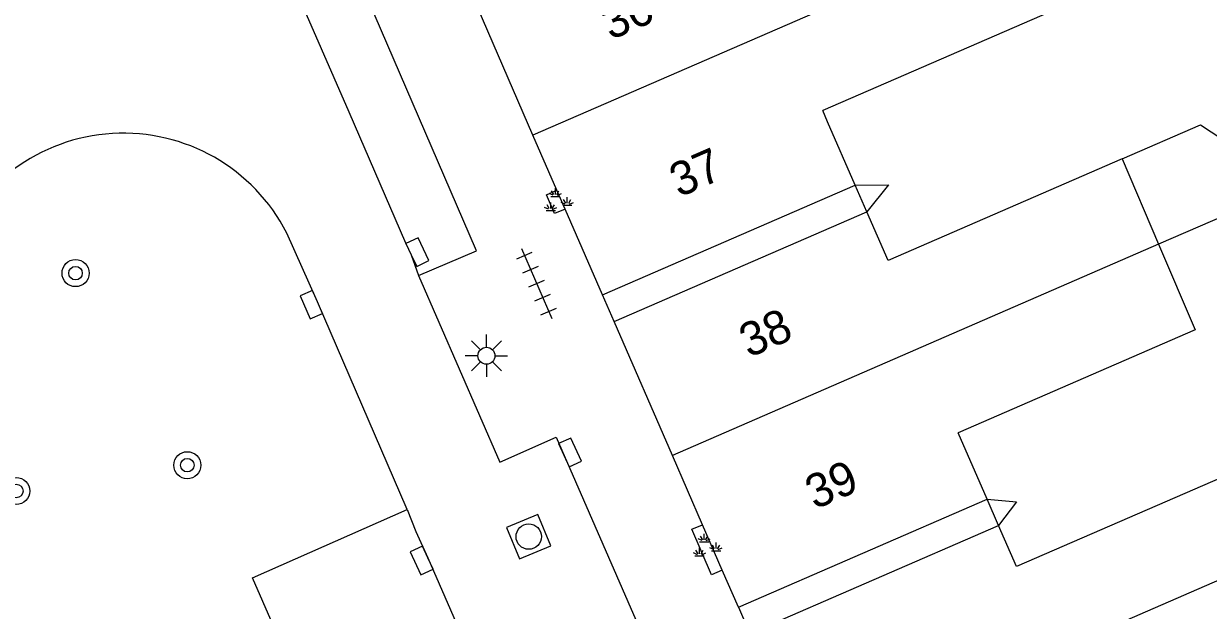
# Model space of a CAD drawing. Extents: x 132998 to 136004, y 396998 to 398512.
# Drawn here: x 133200.28 to 133235.3, y 397162.85 to 397180.2 of the extents above; entities that cross this region are included whole.
import ezdxf

# ---------------------------------------------------------------- set-up
doc = ezdxf.new("R2010")
doc.units = 0
for name, color, linetype in [('gg-afsc-erfafscheiding', 7, 'Continuous'), ('gg-anno-huisnummerreeks BGT', 7, 'Continuous'), ('gg-bbg-gedigitaliseerde bebouwing', 7, 'Continuous'), ('gg-bbg-gedigitaliseerde bebouwing onder overbouw', 7, 'Continuous'), ('gg-bbg-gedigitaliseerde overbouw', 7, 'Continuous'), ('gg-bbg-hoofdgebouw', 7, 'Continuous'), ('gg-bbg-luifel en loopbrug', 7, 'Continuous'), ('gg-bbg-pand overbouw', 7, 'Continuous'), ('gg-bbg-tussenscheiding', 7, 'Continuous'), ('gg-knt-verharding', 7, 'Continuous'), ('gg-knt-verharding nz', 7, 'Continuous'), ('gt-symb-boom', 7, 'Continuous'), ('gt-symb-groenvak', 7, 'Continuous'), ('gt-symb-kolk', 7, 'Continuous'), ('gt-symb-lichtmast', 7, 'Continuous'), ('gt-symb-rioolschacht', 7, 'Continuous'), ('gt-symb-tegel verharding', 7, 'Continuous')]:
    doc.layers.add(name, color=color, linetype=linetype)

# ---------------------------------------------------------------- blocks, each defined once
blk = doc.blocks.new('gt0-GRVAK')
at = {"layer": 'gt-symb-groenvak'}
for p, q in [((-0.047, 0.214), (-0.047, 0.393)), ((-0.11, 0.189), (-0.228, 0.24)), ((-0.182, 0.153), (0.088, 0.153)), ((-0.091, 0.211), (-0.156, 0.322)), ((-0.004, 0.211), (0.061, 0.322)), ((0.015, 0.189), (0.133, 0.24)), ((0.262, -0.052), (0.197, 0.059)), ((0.305, -0.049), (0.305, 0.13)), ((0.349, -0.052), (0.414, 0.059)), ((-0.245, -0.228), (-0.363, -0.177)), ((-0.318, -0.264), (-0.047, -0.264)), ((-0.226, -0.206), (-0.291, -0.095)), ((-0.183, -0.203), (-0.183, -0.024)), ((-0.139, -0.206), (-0.074, -0.095)), ((-0.12, -0.228), (-0.002, -0.177)), ((0.243, -0.074), (0.125, -0.023)), ((0.17, -0.11), (0.441, -0.11)), ((0.368, -0.074), (0.486, -0.023))]:
    blk.add_line(p, q, dxfattribs=at)
blk = doc.blocks.new('gt0-KOLK')
at = {"layer": 'gt-symb-kolk'}
blk.add_lwpolyline([(0, 0), (0.375, 0), (0.375, 0.4), (-0.375, 0.4), (-0.375, 0), (0, 0)], dxfattribs=at)
blk = doc.blocks.new('gt0-BOOM')
at = {"layer": 'gt-symb-boom'}
for radius in [0.4, 0.2]:
    blk.add_circle((0, 0), radius, dxfattribs=at)
blk = doc.blocks.new('gt0-LMAST')
at = {"layer": 'gt-symb-lichtmast'}
for p, q in [((-0.182, 0.173), (-0.447, 0.438)), ((-0.005, 0.246), (-0.005, 0.621)), ((0.172, 0.173), (0.437, 0.438)), ((-0.255, -0.004), (-0.63, -0.004)), ((-0.182, -0.181), (-0.447, -0.446)), ((-0.005, -0.254), (-0.005, -0.629)), ((0.437, -0.446), (0.172, -0.181)), ((0.245, -0.004), (0.62, -0.004))]:
    blk.add_line(p, q, dxfattribs=at)
blk.add_circle((-0.005, -0.004), 0.25, dxfattribs=at)
blk = doc.blocks.new('gt0-TEG1')
at = {"layer": 'gt-symb-tegel verharding'}
for p, q in [((-1.125, 0), (1.125, 0)), ((-0.9, -0.25), (-0.9, 0.25)), ((-0.45, -0.25), (-0.45, 0.25)), ((0, -0.25), (0, 0.25)), ((0.45, -0.25), (0.45, 0.25)), ((0.9, -0.25), (0.9, 0.25))]:
    blk.add_line(p, q, dxfattribs=at)
blk = doc.blocks.new('gt0-RS')
at = {"layer": 'gt-symb-rioolschacht'}
blk.add_lwpolyline([(-0.5, -0.5), (0.5, -0.5), (0.5, 0.5), (-0.5, 0.5)], close=True, dxfattribs=at)
blk.add_circle((0, 0), 0.375, dxfattribs=at)

msp = doc.modelspace()

# ---------------------------------------------------------------- linework, layer by layer
at = {"layer": 'gg-afsc-erfafscheiding'}
for points in [[(133224.863, 397175.424), (133225.843, 397175.433), (133225.204, 397174.64)], [(133228.762, 397166.135), (133229.632, 397166.06), (133229.1, 397165.358)]]:
    msp.add_lwpolyline(points, dxfattribs=at)
at = {"layer": 'gg-bbg-gedigitaliseerde bebouwing'}
for p, q in [((133231.428, 397180.9), (133223.903, 397177.63)), ((133224.046, 397177.302), (133223.903, 397177.63)), ((133224.863, 397175.424), (133224.046, 397177.302)), ((133232.753, 397176.204), (133225.833, 397173.196)), ((133232.753, 397176.204), (133233.831, 397173.675)), ((133225.833, 397173.196), (133225.204, 397174.64)), ((133233.831, 397173.675), (133234.91, 397171.145)), ((133234.91, 397171.145), (133227.907, 397168.101)), ((133228.762, 397166.135), (133227.907, 397168.101)), ((133229.628, 397164.144), (133229.1, 397165.358))]:
    msp.add_line(p, q, dxfattribs=at)
msp.add_lwpolyline([(133237.519, 397167.139), (133237.354, 397167.503), (133229.628, 397164.144)], dxfattribs=at)
at = {"layer": 'gg-bbg-gedigitaliseerde bebouwing onder overbouw'}
for p, q in [((133217.394, 397172.177), (133224.863, 397175.424)), ((133217.735, 397171.393), (133225.204, 397174.64)), ((133221.41, 397162.939), (133228.762, 397166.135)), ((133221.748, 397162.162), (133229.1, 397165.358))]:
    msp.add_line(p, q, dxfattribs=at)
at = {"layer": 'gg-bbg-gedigitaliseerde overbouw'}
for p, q in [((133225.204, 397174.64), (133224.863, 397175.424)), ((133229.1, 397165.358), (133228.762, 397166.135))]:
    msp.add_line(p, q, dxfattribs=at)
at = {"layer": 'gg-bbg-hoofdgebouw'}
for p, q in [((133215.339, 397176.905), (133213.717, 397180.636)), ((133216.047, 397175.276), (133215.339, 397176.905)), ((133216.29, 397174.718), (133216.047, 397175.276)), ((133217.394, 397172.177), (133216.29, 397174.718)), ((133219.459, 397167.427), (133217.735, 397171.393)), ((133220.347, 397165.383), (133219.459, 397167.427)), ((133220.934, 397164.034), (133220.347, 397165.383)), ((133221.41, 397162.939), (133220.934, 397164.034))]:
    msp.add_line(p, q, dxfattribs=at)
at = {"layer": 'gg-bbg-luifel en loopbrug'}
msp.add_lwpolyline([(133232.753, 397176.204), (133235.068, 397177.211), (133237.816, 397175.407), (133233.831, 397173.675)], dxfattribs=at)
at = {"layer": 'gg-bbg-pand overbouw'}
for p, q in [((133217.735, 397171.393), (133217.394, 397172.177)), ((133221.41, 397162.939), (133221.748, 397162.162))]:
    msp.add_line(p, q, dxfattribs=at)
at = {"layer": 'gg-bbg-tussenscheiding'}
for p, q in [((133228.773, 397182.745), (133215.339, 397176.905)), ((133233.831, 397173.675), (133219.459, 397167.427)), ((133238.49, 397164.998), (133223.372, 397158.426))]:
    msp.add_line(p, q, dxfattribs=at)
at = {"layer": 'gg-knt-verharding'}
for points in [[(133211.956, 397172.754), (133213.674, 397173.48), (133208.956, 397184.401), (133201.867, 397200.282), (133200.48, 397203.69)], [(133216.29, 397174.718), (133215.978, 397174.582), (133215.735, 397175.141), (133216.047, 397175.276)], [(133211.616, 397165.832), (133208.969, 397171.969), (133208.06, 397174.009)], [(133211.956, 397172.754), (133214.358, 397167.234), (133216.02, 397167.97), (133226.755, 397143.354)], [(133217.493, 397139.873), (133207.049, 397163.812), (133211.616, 397165.832)], [(133220.934, 397164.034), (133220.616, 397163.896), (133220.032, 397165.246), (133220.347, 397165.383)]]:
    msp.add_lwpolyline(points, dxfattribs=at)
msp.add_arc((133203.23, 397171.535), 5.427, 27.124, 159.7288, dxfattribs=at)
at = {"layer": 'gg-knt-verharding nz'}
for points in [[(133200.48, 397203.69), (133198.81, 397202.97), (133209.893, 397177.589)], [(133209.893, 397177.589), (133211.57, 397173.717), (133211.74, 397173.359), (133211.956, 397172.754)], [(133211.616, 397165.832), (133211.877, 397165.185), (133212.23, 397164.405), (133216.207, 397155.262), (133222.074, 397141.852)]]:
    msp.add_lwpolyline(points, dxfattribs=at)

# ---------------------------------------------------------------- block references
at = {"layer": 'gt-symb-boom'}
for p in [(133201.818, 397172.823), (133205.12, 397167.142), (133200.065, 397166.379)]:
    msp.add_blockref('gt0-BOOM', p, dxfattribs=at)
at = {"layer": 'gt-symb-groenvak'}
for p in [(133216.047, 397174.939), (133220.446, 397164.723)]:
    msp.add_blockref('gt0-GRVAK', p, dxfattribs=at)
at = {"layer": 'gt-symb-kolk'}
for p, rotation in [((133211.74, 397173.359), -64.58839927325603), ((133208.969, 397171.969), 113.33404127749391), ((133216.252, 397167.438), -65.4849292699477), ((133212.23, 397164.405), 114.33487429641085)]:
    msp.add_blockref('gt0-KOLK', p, dxfattribs=dict(at, rotation=rotation))
at = {"layer": 'gt-symb-lichtmast'}
msp.add_blockref('gt0-LMAST', (133213.967, 397170.384), dxfattribs=at)
at = {"layer": 'gt-symb-rioolschacht', "rotation": -157.35809990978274}
msp.add_blockref('gt0-RS', (133215.214, 397165.03), dxfattribs=at)
at = {"layer": 'gt-symb-tegel verharding', "rotation": -66.61335784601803}
msp.add_blockref('gt0-TEG1', (133215.447, 397172.515), dxfattribs=at)

# ---------------------------------------------------------------- texts
at = {"layer": 'gg-anno-huisnummerreeks BGT'}
for s, p in [('36', (133217.636, 397179.704)), ('37', (133219.659, 397175.052)), ('38', (133221.721, 397170.308)), ('39', (133223.671, 397165.821))]:
    msp.add_text(s, height=1, rotation=23.5, dxfattribs=at).set_placement(p)

doc.saveas('drawing.dxf')
